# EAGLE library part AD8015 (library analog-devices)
Wideband/Differential Output Transimpedance Amplifier Source: http://www.analog.com/static/imported-files/data_sheets/AD8015.pdf
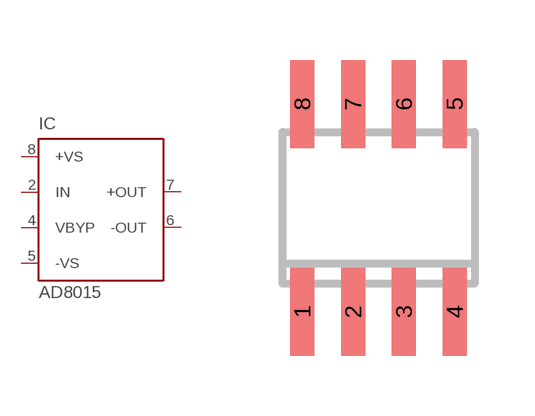
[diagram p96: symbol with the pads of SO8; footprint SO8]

Designator prefix IC

## AD8015 (MPN: AD8015ARZ; OC_FARNELL: 1464812; OC_NEWARK: 19M8870)  [SO8]
2  IN  in
4  VBYP  in
5  -VS  in
6  -OUT  out
7  +OUT  out
8  +VS  in

## Footprint SO8 (pad centres in mm)
8-Lead Small Outline IC (SO-8) Source: http://www.analog.com/UploadedFiles/Data_Sheets/703465986AD8611_2_0.pdf
smd 0.6 x 2.2: 1 -1.905,-2.6; 2 -0.635,-2.6; 3 0.635,-2.6; 4 1.905,-2.6; 5 1.905,2.6; 6 0.635,2.6; 7 -0.635,2.6; 8 -1.905,2.6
